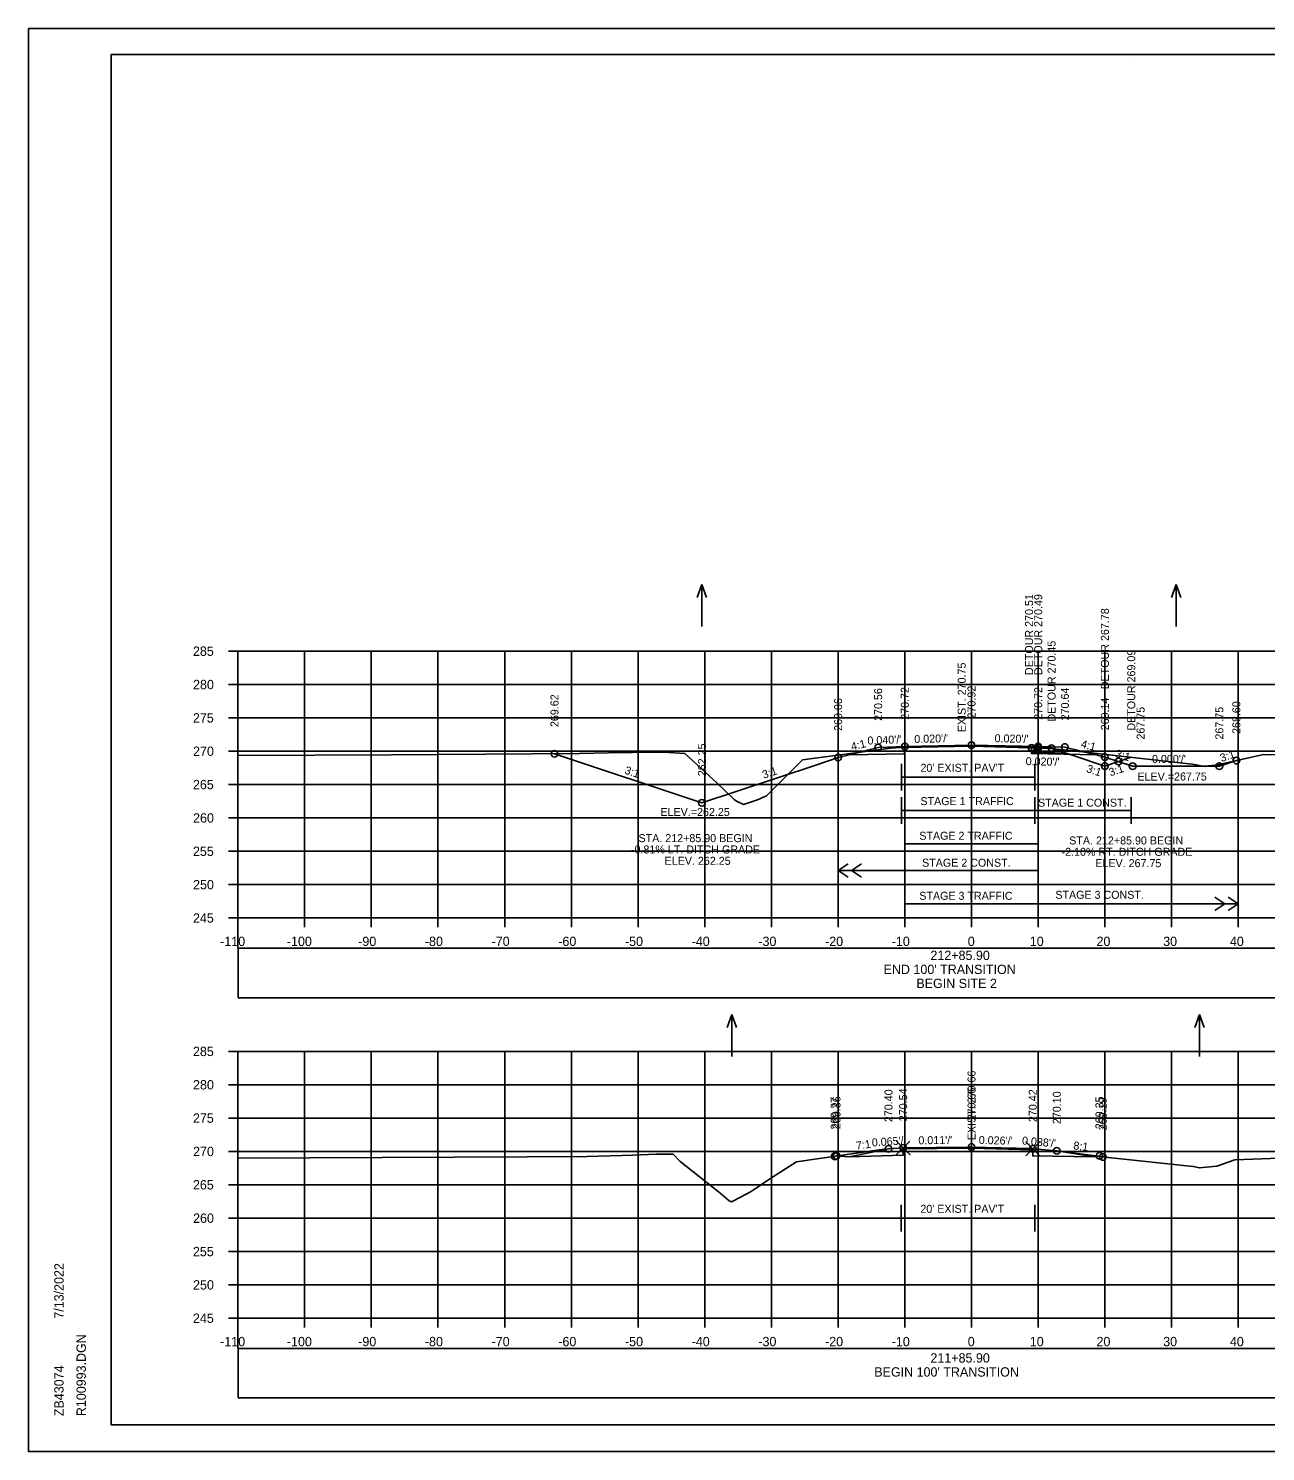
# Model space of a CAD drawing. Extents: x 4667 to 1632277, y -2100 to 724501.
# Drawn here: x 5635.8 to 5821.3, y -1963.8 to -1750.4 of the extents above; entities that cross this region are included whole.
import ezdxf

# ---------------------------------------------------------------- set-up
doc = ezdxf.new("R2010")
doc.units = 0
for name, color, linetype in [('R_Alt Surface', 7, 'Continuous'), ('R_Axis', 7, 'Continuous'), ('R_Axis Annot', 7, 'Continuous'), ('R_Border', 7, 'Continuous'), ('R_Detour', 7, 'Continuous'), ('R_Detour Annot', 7, 'Continuous'), ('R_Exist Surface', 7, 'Continuous'), ('R_Fin Surface', 7, 'Continuous'), ('R_Fin Surface Annot', 7, 'Continuous'), ('R_Grid', 7, 'Continuous'), ('R_No Plot', 7, 'Continuous'), ('R_Proposed CofA', 7, 'Continuous'), ('R_Temp Easement', 7, 'Continuous'), ('R_Water Annot', 7, 'Continuous'), ('T_Notes', 7, 'Continuous')]:
    doc.layers.add(name, color=color, linetype=linetype)

msp = doc.modelspace()

# ---------------------------------------------------------------- linework, layer by layer
at = {"layer": 'R_Alt Surface'}
msp.add_lwpolyline([(5758.82, -1859.32), (5767.15, -1859.15), (5767.15, -1858.23), (5777.18, -1858.03), (5786.16, -1858.21), (5786.16, -1859.13), (5795.89, -1859.32)], dxfattribs=at)
at = {"layer": 'R_Axis'}
for p, q in [((5665.78, -1843.78), (5667.18, -1843.78)), ((5667.18, -1883.78), (5667.18, -1843.78)), ((5665.78, -1848.78), (5667.18, -1848.78)), ((5665.78, -1853.78), (5667.18, -1853.78)), ((5665.78, -1858.78), (5667.18, -1858.78)), ((5665.78, -1863.78), (5667.18, -1863.78)), ((5665.78, -1868.78), (5667.18, -1868.78)), ((5665.78, -1873.78), (5667.18, -1873.78)), ((5665.78, -1878.78), (5667.18, -1878.78)), ((5665.78, -1883.78), (5667.18, -1883.78)), ((5667.18, -1883.78), (5947.18, -1883.78)), ((5667.18, -1885.18), (5667.18, -1883.78)), ((5677.18, -1885.18), (5677.18, -1883.78)), ((5687.18, -1885.18), (5687.18, -1883.78)), ((5697.18, -1885.18), (5697.18, -1883.78)), ((5707.18, -1885.18), (5707.18, -1883.78)), ((5717.18, -1885.18), (5717.18, -1883.78)), ((5727.18, -1885.18), (5727.18, -1883.78)), ((5737.18, -1885.18), (5737.18, -1883.78)), ((5747.18, -1885.18), (5747.18, -1883.78)), ((5757.18, -1885.18), (5757.18, -1883.78)), ((5767.18, -1885.18), (5767.18, -1883.78)), ((5777.18, -1885.18), (5777.18, -1883.78)), ((5787.18, -1885.18), (5787.18, -1883.78)), ((5797.18, -1885.18), (5797.18, -1883.78)), ((5807.18, -1885.18), (5807.18, -1883.78)), ((5817.18, -1885.18), (5817.18, -1883.78)), ((5665.78, -1903.78), (5667.18, -1903.78)), ((5667.18, -1943.78), (5667.18, -1903.78)), ((5665.78, -1908.78), (5667.18, -1908.78)), ((5665.78, -1913.78), (5667.18, -1913.78)), ((5665.78, -1918.78), (5667.18, -1918.78)), ((5665.78, -1923.78), (5667.18, -1923.78)), ((5665.78, -1928.78), (5667.18, -1928.78)), ((5665.78, -1933.78), (5667.18, -1933.78)), ((5665.78, -1938.78), (5667.18, -1938.78)), ((5665.78, -1943.78), (5667.18, -1943.78)), ((5667.18, -1943.78), (5947.18, -1943.78)), ((5667.18, -1945.18), (5667.18, -1943.78)), ((5677.18, -1945.18), (5677.18, -1943.78)), ((5687.18, -1945.18), (5687.18, -1943.78)), ((5697.18, -1945.18), (5697.18, -1943.78)), ((5707.18, -1945.18), (5707.18, -1943.78)), ((5717.18, -1945.18), (5717.18, -1943.78)), ((5727.18, -1945.18), (5727.18, -1943.78)), ((5737.18, -1945.18), (5737.18, -1943.78)), ((5747.18, -1945.18), (5747.18, -1943.78)), ((5757.18, -1945.18), (5757.18, -1943.78)), ((5767.18, -1945.18), (5767.18, -1943.78)), ((5777.18, -1945.18), (5777.18, -1943.78)), ((5787.18, -1945.18), (5787.18, -1943.78)), ((5797.18, -1945.18), (5797.18, -1943.78)), ((5807.18, -1945.18), (5807.18, -1943.78)), ((5817.18, -1945.18), (5817.18, -1943.78))]:
    msp.add_line(p, q, dxfattribs=at)
at = {"layer": 'R_Border'}
for p, q in [((5648.18, -1754.32), (5964.36, -1754.32)), ((5648.18, -1959.78), (5648.18, -1754.32)), ((5800.7, -1754.58), (5800.7, -1754.58)), ((5800.7, -1754.58), (5800.7, -1754.58)), ((5648.18, -1959.78), (5648.18, -1959.78)), ((5964.36, -1959.78), (5648.18, -1959.78))]:
    msp.add_line(p, q, dxfattribs=at)
at = {"layer": 'R_Detour'}
for points in [[(5786.16, -1858.28), (5787.18, -1858.3), (5789.18, -1858.34), (5792.44, -1859.42), (5797.18, -1861), (5801.13, -1859.69)], [(5786.17, -1858.94), (5786.16, -1858.28)], [(5791.31, -1859.05), (5786.17, -1858.94)]]:
    msp.add_lwpolyline(points, dxfattribs=at)
at = {"layer": 'R_Exist Surface'}
for points in [[(5667.18, -1859.42), (5690.21, -1859.3), (5718.41, -1859.14), (5722.73, -1859.02), (5729.94, -1858.9), (5731, -1858.94), (5734.2, -1859.12), (5738.99, -1863.54), (5741.59, -1866.01), (5741.93, -1866.27), (5743.01, -1866.75), (5745.11, -1866.07), (5746.42, -1865.46), (5749.45, -1862.45), (5751.86, -1860.08), (5764.66, -1858.37), (5764.89, -1858.34), (5765.1, -1858.31), (5765.13, -1858.31), (5767.15, -1858.15), (5776.88, -1858.03), (5777.27, -1858.03), (5785.83, -1858.27), (5786.16, -1858.28), (5788.1, -1858.31), (5788.2, -1858.32), (5793.15, -1858.79), (5793.28, -1858.8), (5793.82, -1858.86), (5810.19, -1860.72), (5810.3, -1860.74), (5812.14, -1861.05), (5812.18, -1861.04), (5814.2, -1860.8), (5814.53, -1860.72), (5820.97, -1859.26), (5835.05, -1859.39)], [(5667.18, -1919.81), (5710.52, -1919.59), (5719.55, -1919.54), (5726.38, -1919.32), (5729.9, -1919.2), (5730.17, -1919.21), (5732.46, -1919.2), (5733.47, -1920.27), (5739.46, -1924.99), (5740.83, -1926.19), (5741.22, -1926.32), (5741.47, -1926.16), (5744.14, -1924.77), (5746.94, -1922.88), (5750.94, -1920.33), (5763.31, -1918.55), (5764.74, -1918.38), (5766.86, -1918.24), (5766.94, -1918.24), (5776.71, -1918.13), (5777.11, -1918.12), (5786.1, -1918.36), (5786.35, -1918.37), (5786.46, -1918.37), (5789.91, -1918.68), (5796.97, -1919.61), (5797.21, -1919.64), (5810.34, -1921.02), (5810.5, -1921.04), (5811.33, -1921.24), (5811.36, -1921.24), (5813.91, -1921), (5813.94, -1921), (5816.64, -1920.01), (5816.66, -1920.01), (5828.71, -1919.57)]]:
    msp.add_lwpolyline(points, dxfattribs=at)
at = {"layer": 'R_Fin Surface'}
msp.add_lwpolyline([(5714.65, -1859.16), (5736.76, -1866.53), (5741.72, -1864.88), (5753.82, -1860.85), (5757.18, -1859.73), (5758.82, -1859.32), (5763.18, -1858.23), (5767.18, -1858.07), (5777.18, -1857.87), (5787.18, -1858.07), (5791.18, -1858.15), (5795.89, -1859.32), (5797.18, -1859.65), (5801.34, -1861.03), (5814.34, -1861.03), (5816.89, -1860.19)], dxfattribs=at)
at = {"layer": 'R_Grid'}
for p, q in [((5667.18, -1843.78), (5947.18, -1843.78)), ((5667.18, -1883.78), (5667.18, -1843.78)), ((5677.18, -1883.78), (5677.18, -1843.78)), ((5687.18, -1883.78), (5687.18, -1843.78)), ((5697.18, -1883.78), (5697.18, -1843.78)), ((5707.18, -1883.78), (5707.18, -1843.78)), ((5717.18, -1883.78), (5717.18, -1843.78)), ((5727.18, -1883.78), (5727.18, -1843.78)), ((5737.18, -1883.78), (5737.18, -1843.78)), ((5747.18, -1883.78), (5747.18, -1843.78)), ((5757.18, -1883.78), (5757.18, -1843.78)), ((5767.18, -1883.78), (5767.18, -1843.78)), ((5777.18, -1883.78), (5777.18, -1843.78)), ((5787.18, -1883.78), (5787.18, -1843.78)), ((5797.18, -1883.78), (5797.18, -1843.78)), ((5807.18, -1883.78), (5807.18, -1843.78)), ((5817.18, -1883.78), (5817.18, -1843.78)), ((5667.18, -1848.78), (5947.18, -1848.78)), ((5667.18, -1853.78), (5947.18, -1853.78)), ((5667.18, -1858.78), (5947.18, -1858.78)), ((5667.18, -1863.78), (5947.18, -1863.78)), ((5667.18, -1868.78), (5947.18, -1868.78)), ((5667.18, -1873.78), (5947.18, -1873.78)), ((5667.18, -1878.78), (5947.18, -1878.78)), ((5667.18, -1883.78), (5947.18, -1883.78)), ((5667.18, -1903.78), (5947.18, -1903.78)), ((5667.18, -1943.78), (5667.18, -1903.78)), ((5677.18, -1943.78), (5677.18, -1903.78)), ((5687.18, -1943.78), (5687.18, -1903.78)), ((5697.18, -1943.78), (5697.18, -1903.78)), ((5707.18, -1943.78), (5707.18, -1903.78)), ((5717.18, -1943.78), (5717.18, -1903.78)), ((5727.18, -1943.78), (5727.18, -1903.78)), ((5737.18, -1943.78), (5737.18, -1903.78)), ((5747.18, -1943.78), (5747.18, -1903.78)), ((5757.18, -1943.78), (5757.18, -1903.78)), ((5767.18, -1943.78), (5767.18, -1903.78)), ((5777.18, -1943.78), (5777.18, -1903.78)), ((5787.18, -1943.78), (5787.18, -1903.78)), ((5797.18, -1943.78), (5797.18, -1903.78)), ((5807.18, -1943.78), (5807.18, -1903.78)), ((5817.18, -1943.78), (5817.18, -1903.78)), ((5667.18, -1908.78), (5947.18, -1908.78)), ((5667.18, -1913.78), (5947.18, -1913.78)), ((5667.18, -1918.78), (5947.18, -1918.78)), ((5667.18, -1923.78), (5947.18, -1923.78)), ((5667.18, -1928.78), (5947.18, -1928.78)), ((5667.18, -1933.78), (5947.18, -1933.78)), ((5667.18, -1938.78), (5947.18, -1938.78)), ((5667.18, -1943.78), (5947.18, -1943.78))]:
    msp.add_line(p, q, dxfattribs=at)
at = {"layer": 'R_No Plot'}
for p, q in [((5635.78, -1750.43), (5969.12, -1750.43)), ((5667.18, -1885.18), (5667.18, -1888.26)), ((5667.18, -1945.18), (5667.18, -1948.26)), ((5635.78, -1963.76), (5969.12, -1963.76))]:
    msp.add_line(p, q, dxfattribs=at)
for points in [[(5635.78, -1750.43), (5969.12, -1750.43), (5969.12, -1963.77), (5635.78, -1963.77)], [(5882.1, -1754.32), (5901.72, -1754.32), (5901.72, -1764.2), (5917.84, -1764.2), (5941.04, -1764.2), (5941.04, -1788.53), (5964.36, -1788.53), (5964.36, -1959.78), (5648.18, -1959.78), (5648.18, -1754.32)]]:
    msp.add_lwpolyline(points, close=True, dxfattribs=at)
for points in [[(5766.94, -1918.24), (5765.94, -1917.24), (5766.94, -1918.24), (5765.94, -1919.24), (5766.94, -1918.24), (5767.94, -1919.24), (5766.94, -1918.24), (5767.94, -1917.24)], [(5786.35, -1918.37), (5785.35, -1917.37), (5786.35, -1918.37), (5785.35, -1919.37), (5786.35, -1918.37), (5787.35, -1919.37), (5786.35, -1918.37), (5787.35, -1917.37)], [(5756.67, -1919.51), (5756.93, -1919.42), (5758.82, -1919.57), (5764.73, -1918.38), (5766.93, -1918.24), (5777.18, -1918.12), (5786.36, -1918.37), (5789.96, -1918.68), (5795.55, -1919.57), (5796.36, -1919.44), (5796.85, -1919.6)], [(5758.82, -1919.57), (5766.94, -1919.32), (5766.94, -1918.4), (5777.18, -1918.29), (5786.35, -1918.53), (5786.35, -1919.45), (5795.55, -1919.57)]]:
    msp.add_lwpolyline(points, dxfattribs=at)
for centre in [(5763.18, -1858.23), (5767.18, -1858.07), (5777.18, -1857.87), (5786.16, -1858.28), (5787.18, -1858.07), (5787.18, -1858.3), (5789.18, -1858.34), (5791.18, -1858.15), (5714.65, -1859.16), (5757.18, -1859.73), (5797.18, -1859.65), (5799.22, -1860.32), (5816.89, -1860.19), (5797.18, -1861), (5801.34, -1861.03), (5814.34, -1861.03), (5736.76, -1866.53), (5764.73, -1918.38), (5766.93, -1918.24), (5777.18, -1918.12), (5786.36, -1918.37), (5756.67, -1919.51), (5756.93, -1919.42), (5789.96, -1918.68), (5796.36, -1919.44), (5796.85, -1919.6)]:
    msp.add_circle(centre, 0.5, dxfattribs=at)
at = {"layer": 'R_Proposed CofA'}
for points in [[(5667.23, -1895.73), (5947.13, -1895.73), (5947.13, -1888.31), (5667.23, -1888.31)], [(5667.23, -1955.73), (5947.13, -1955.73), (5947.13, -1948.31), (5667.23, -1948.31)]]:
    msp.add_lwpolyline(points, close=True, dxfattribs=at)
at = {"layer": 'R_Temp Easement'}
for p, q in [((5766.66, -1864.66), (5766.66, -1860.66)), ((5786.66, -1864.66), (5786.66, -1860.66)), ((5766.66, -1862.66), (5786.66, -1862.66)), ((5766.66, -1869.66), (5766.66, -1865.66)), ((5786.66, -1869.66), (5786.66, -1865.66)), ((5801.13, -1869.66), (5801.13, -1865.66)), ((5766.66, -1867.66), (5786.66, -1867.66)), ((5801.13, -1867.66), (5786.66, -1867.66)), ((5767.18, -1874.66), (5767.18, -1870.66)), ((5787.18, -1874.66), (5787.18, -1870.66)), ((5787.18, -1872.66), (5767.18, -1872.66)), ((5787.18, -1878.66), (5787.18, -1874.66)), ((5757.18, -1876.66), (5758.68, -1875.66)), ((5787.18, -1876.66), (5757.18, -1876.66)), ((5757.18, -1876.66), (5758.68, -1877.66)), ((5759.18, -1876.66), (5760.68, -1875.66)), ((5759.18, -1876.66), (5760.68, -1877.66)), ((5767.18, -1883.66), (5767.18, -1879.66)), ((5787.18, -1883.66), (5787.18, -1879.66)), ((5815.18, -1881.66), (5813.68, -1880.66)), ((5817.18, -1881.66), (5815.68, -1880.66)), ((5787.18, -1881.66), (5767.18, -1881.66)), ((5787.18, -1881.66), (5817.18, -1881.66)), ((5815.18, -1881.66), (5813.68, -1882.66)), ((5817.18, -1881.66), (5815.68, -1882.66)), ((5766.65, -1930.78), (5766.65, -1926.78)), ((5786.65, -1930.78), (5786.65, -1926.78)), ((5766.65, -1928.78), (5786.65, -1928.78))]:
    msp.add_line(p, q, dxfattribs=at)
at = {"layer": 'R_Water Annot'}
for p, q in [((5736.76, -1833.78), (5736.06, -1835.71)), ((5736.76, -1840.07), (5736.76, -1833.78)), ((5736.76, -1833.78), (5737.46, -1835.71)), ((5807.84, -1833.78), (5807.14, -1835.71)), ((5807.84, -1840.07), (5807.84, -1833.78)), ((5807.84, -1833.78), (5808.54, -1835.71)), ((5741.22, -1898.26), (5740.52, -1900.18)), ((5741.22, -1904.54), (5741.22, -1898.26)), ((5741.22, -1898.26), (5741.92, -1900.18)), ((5811.36, -1898.26), (5810.66, -1900.18)), ((5811.36, -1904.54), (5811.36, -1898.26)), ((5811.36, -1898.26), (5812.06, -1900.18))]:
    msp.add_line(p, q, dxfattribs=at)
at = {"layer": 'T_Notes'}
msp.add_line((5789.18, -1858.27), (5789.28, -1858.37), dxfattribs=at)
for points in [[(5777.6, -1858.04), (5786.16, -1858.21), (5789.18, -1858.27)], [(5777.6, -1858.04), (5785.83, -1858.27), (5786.16, -1858.28), (5789.18, -1858.34), (5789.28, -1858.37)]]:
    msp.add_lwpolyline(points, dxfattribs=at)

# ---------------------------------------------------------------- texts
at = {"layer": 'R_Axis Annot'}
for s, p in [('285', (5660.44, -1844.48)), ('280', (5660.46, -1849.48)), ('275', (5660.44, -1854.48)), ('270', (5660.46, -1859.48)), ('265', (5660.44, -1864.48)), ('260', (5660.46, -1869.48)), ('255', (5660.44, -1874.48)), ('250', (5660.46, -1879.48)), ('245', (5660.44, -1884.48)), ('-110', (5664.52, -1887.98)), ('-100', (5674.52, -1887.98)), ('-90', (5685.22, -1887.98)), ('-80', (5695.22, -1887.98)), ('-70', (5705.22, -1887.98)), ('-60', (5715.22, -1887.98)), ('-50', (5725.22, -1887.98)), ('-40', (5735.22, -1887.98)), ('-30', (5745.22, -1887.98)), ('-20', (5755.22, -1887.98)), ('-10', (5765.22, -1887.98)), ('0', (5776.62, -1887.98)), ('10', (5785.92, -1887.98)), ('20', (5795.92, -1887.98)), ('30', (5805.92, -1887.98)), ('40', (5815.92, -1887.98)), ('212+85.90', (5771.02, -1890.08)), ("END 100' TRANSITION", (5764, -1892.18)), ('BEGIN SITE 2', (5768.91, -1894.28)), ('285', (5660.44, -1904.48)), ('280', (5660.46, -1909.48)), ('275', (5660.44, -1914.48)), ('270', (5660.46, -1919.48)), ('265', (5660.44, -1924.48)), ('260', (5660.46, -1929.48)), ('255', (5660.44, -1934.48)), ('250', (5660.46, -1939.48)), ('245', (5660.44, -1944.48)), ('-110', (5664.52, -1947.98)), ('-100', (5674.52, -1947.98)), ('-90', (5685.22, -1947.98)), ('-80', (5695.22, -1947.98)), ('-70', (5705.22, -1947.98)), ('-60', (5715.22, -1947.98)), ('-50', (5725.22, -1947.98)), ('-40', (5735.22, -1947.98)), ('-30', (5745.22, -1947.98)), ('-20', (5755.22, -1947.98)), ('-10', (5765.22, -1947.98)), ('0', (5776.62, -1947.98)), ('10', (5785.92, -1947.98)), ('20', (5795.92, -1947.98)), ('30', (5805.92, -1947.98)), ('40', (5815.92, -1947.98)), ('211+85.90', (5771.02, -1950.43)), ("BEGIN 100' TRANSITION", (5762.6, -1952.53))]:
    msp.add_text(s, height=1.4, dxfattribs=at).set_placement(p)
at = {"layer": 'R_Border'}
for s, p in [('7/13/2022', (5641.05, -1943.85)), ('R100993.DGN', (5644.38, -1958.46)), ('ZB43074', (5641.05, -1958.46))]:
    msp.add_text(s, height=1.4, rotation=90, dxfattribs=at).set_placement(p)
at = {"layer": 'R_Detour Annot'}
for s, rotation, p in [("0.020'/'", 358.8542, (5785.29, -1860.87)), ('3:1', 341.5651, (5794.31, -1861.88)), ('3:1', 18.4349, (5798, -1862.56))]:
    msp.add_text(s, height=1.2, rotation=rotation, dxfattribs=at).set_placement(p)
at = {"layer": 'R_Fin Surface Annot'}
for s, rotation, p in [('DETOUR 270.51', 90, (5786.41, -1847.36)), ('DETOUR 270.49', 90, (5787.78, -1847.36)), ('DETOUR 267.78', 90, (5797.78, -1849.48)), ('DETOUR 270.45', 90, (5789.78, -1854.34)), ('DETOUR 269.09', 90, (5801.73, -1855.69)), ('270.56', 90, (5763.78, -1854.23)), ('270.72', 90, (5767.78, -1854.07)), ('270.92', 90, (5777.78, -1853.87)), ('270.72', 90, (5787.78, -1854.07)), ('270.64', 90, (5791.78, -1854.15)), ('269.62', 90, (5715.25, -1855.16)), ('269.06', 90, (5757.78, -1855.73)), ('269.14', 90, (5797.78, -1855.65)), ('268.60', 90, (5817.49, -1856.19)), ('267.75', 90, (5803.13, -1857.03)), ('267.75', 90, (5814.94, -1857.03)), ('262.25', 90, (5737.36, -1862.53)), ('4:1', 14.0362, (5759.26, -1858.69)), ("0.040'/'", 2.2906, (5761.6, -1857.79)), ("0.020'/'", 1.1458, (5768.61, -1857.54)), ("0.020'/'", 358.8542, (5780.63, -1857.43)), ('4:1', 345.9638, (5793.5, -1858.21)), ('3:1', 341.5651, (5798.63, -1859.6)), ('3:1', 18.4349, (5814.67, -1860.4)), ('3:1', 341.5651, (5725.07, -1862.11)), ('3:1', 18.4349, (5746.03, -1862.92))]:
    msp.add_text(s, height=1.2, rotation=rotation, dxfattribs=at).set_placement(p)
msp.add_text("0.000'/'", height=1.2, dxfattribs=at).set_placement((5804.24, -1860.53))
at = {"layer": 'R_No Plot'}
for s, rotation, p in [('270.66', 90, (5777.78, -1914.12)), ('269.27', 90, (5757.27, -1915.51)), ('269.36', 90, (5757.53, -1915.42)), ('270.40', 90, (5765.33, -1914.38)), ('270.54', 90, (5767.53, -1914.24)), ('270.42', 90, (5786.96, -1914.37)), ('270.10', 90, (5790.56, -1914.68)), ('269.35', 90, (5796.96, -1915.44)), ('269.19', 90, (5797.45, -1915.6)), ('7:1', 7.5946, (5759.94, -1918.52)), ("0.065'/'", 3.719, (5762.27, -1918.04)), ("0.011'/'", 0.6474, (5769.22, -1917.71)), ("0.026'/'", 358.482, (5778.25, -1917.65)), ("0.088'/'", 354.9709, (5784.71, -1917.72)), ('8:1', 353.2902, (5792.4, -1918.46))]:
    msp.add_text(s, height=1.2, rotation=rotation, dxfattribs=at).set_placement(p)
at = {"layer": 'R_Temp Easement'}
for s, p in [('EXIST. 270.75', (5776.31, -1855.93)), ('EXIST. 270.66', (5777.78, -1917.1))]:
    msp.add_text(s, height=1.2, rotation=90, dxfattribs=at).set_placement(p)
for s, height, p in [("20' EXIST. PAV'T", 1.2, (5769.52, -1861.86)), ('STAGE 1 TRAFFIC', 1.2, (5769.52, -1866.86)), ('STAGE 1 CONST.', 1.1985, (5787.15, -1867.09)), ('STAGE 2 TRAFFIC', 1.1985, (5769.35, -1872.05)), ('STAGE 2 CONST.', 1.1985, (5769.77, -1876.09)), ('STAGE 3 TRAFFIC', 1.1985, (5769.35, -1881.05)), ('STAGE 3 CONST.', 1.1985, (5789.75, -1880.9)), ("20' EXIST. PAV'T", 1.2, (5769.51, -1927.98))]:
    msp.add_text(s, height=height, dxfattribs=at).set_placement(p)
at = {"layer": 'R_Water Annot'}
for s, p in [('ELEV.=267.75', (5802.06, -1863.17)), ('ELEV.=262.25', (5730.54, -1868.49)), ('-0.81% LT. DITCH GRADE', (5726.12, -1874.11)), ('STA. 212+85.90 BEGIN', (5727.25, -1872.41)), ('STA. 212+85.90 BEGIN', (5791.83, -1872.76)), ('ELEV. 262.25', (5731.16, -1875.81)), ('-2.10% RT. DITCH GRADE', (5790.68, -1874.46)), ('ELEV. 267.75', (5795.74, -1876.16))]:
    msp.add_text(s, height=1.2, dxfattribs=at).set_placement(p)

doc.saveas('drawing.dxf')
